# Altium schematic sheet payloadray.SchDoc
size A4
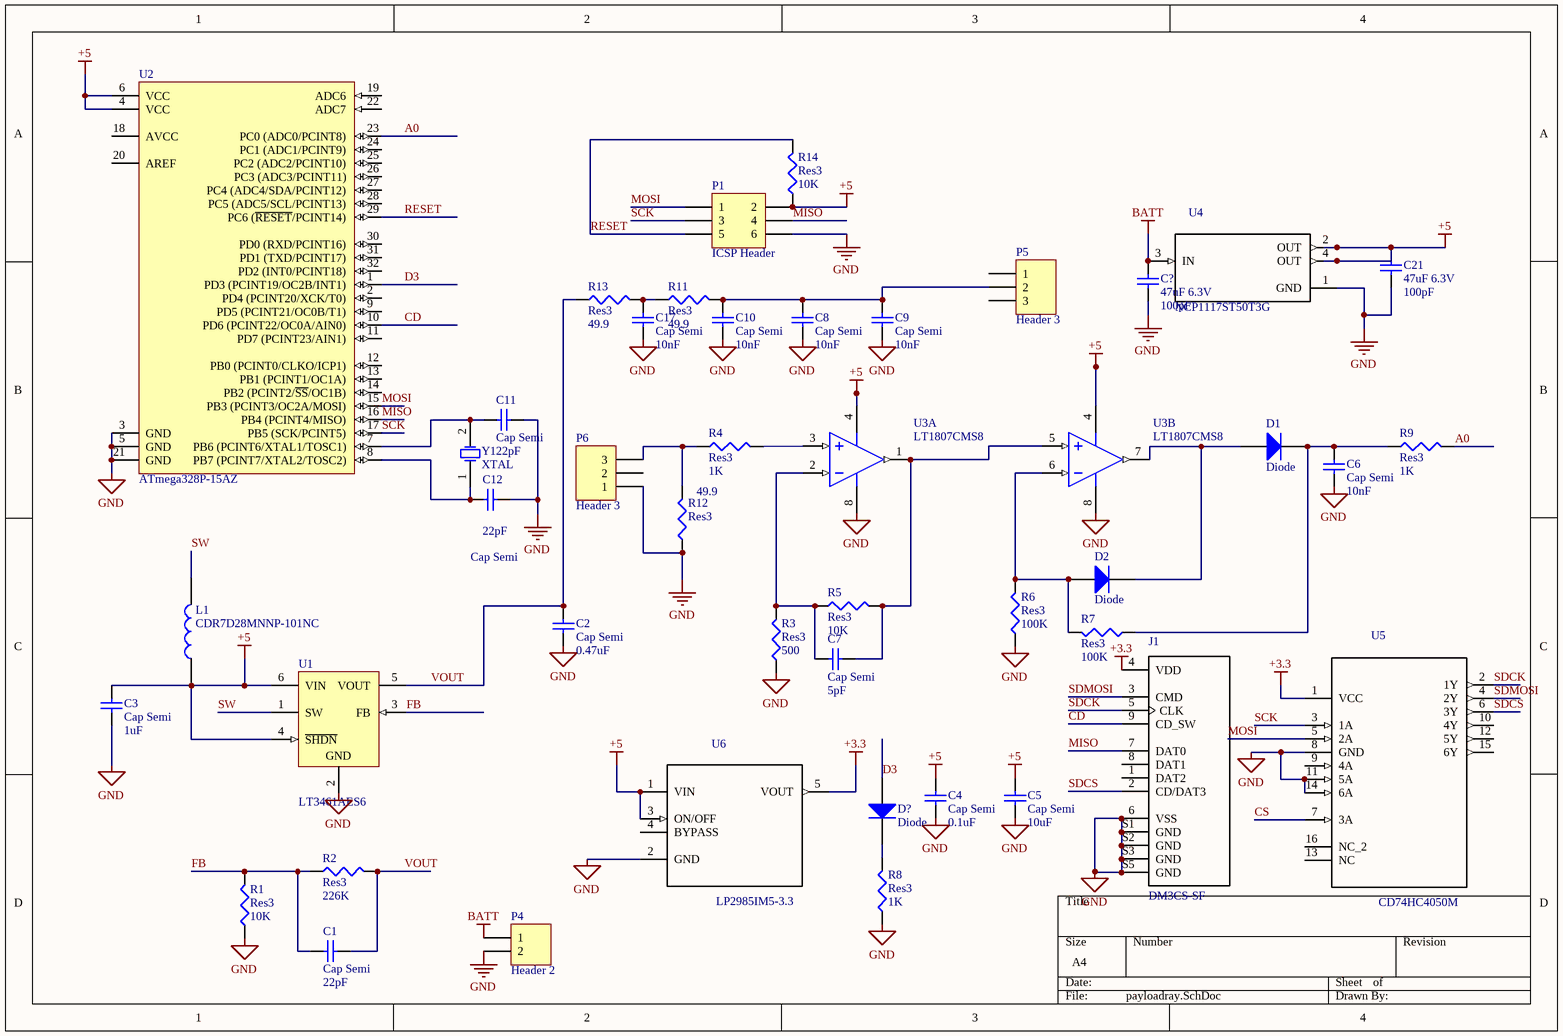
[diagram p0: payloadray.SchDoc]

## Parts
C1  Cap Semi  value 22pF  [C1206]
C2  Cap Semi  value 0.47uF  [C1206]
C3  Cap Semi  value 1uF  [C1206]
C4  Cap Semi  value 0.1uF  [C1206]
C5  Cap Semi  value 10uF  [C1206]
C6  Cap Semi  value 10nF  [C1206]
C7  Cap Semi  value 5pF  [C1206]
C8  Cap Semi  value 10nF  [C1206]
C9  Cap Semi  value 10nF  [C1206]
C10  Cap Semi  value 10nF  [C1206]
C11  Cap Semi  value 22pF  [C1206]
C12  Cap Semi  value 22pF  [C1206]
C17  Cap Semi  value 10nF  [C1206]
C21  47uF 6.3V  value 100pF  [1206]
C?  47uF 6.3V  value 100pF  [1206]
D1  Diode  [SMC]
D2  Diode  [SMC]
D?  Diode  [SMC]
J1  DM3CS-SF  [HRS_DM3CS-SF_DM3CS-SF(Primary)]
L1  CDR7D28MNNP-101NC  [CDR7D28MNNP101NC]
P1  ICSP Header  [HDR2X3]
P4  Header 2  [HDR1X2]
P5  Header 3  [HDR1X3]
P6  Header 3  [HDR1X3]
R1  Res3  value 10K  [J1-0603]
R2  Res3  value 226K  [J1-0603]
R3  Res3  value 500  [J1-0603]
R4  Res3  value 1K  [J1-0603]
R5  Res3  value 10K  [J1-0603]
R6  Res3  value 100K  [J1-0603]
R7  Res3  value 100K  [J1-0603]
R8  Res3  value 1K  [J1-0603]
R9  Res3  value 1K  [J1-0603]
R11  Res3  value 49.9  [J1-0603]
R12  Res3  value 49.9  [J1-0603]
R13  Res3  value 49.9  [J1-0603]
R14  Res3  value 10K  [J1-0603]
U1  LT3461AES6  [LT-S6-6-TSOT-23_N]
U2  ATmega328P-15AZ  [32MA_N]
U3  LT1807CMS8  [LT-MS8-8_N]  (parts A,B of 2)
U4  NCP1117ST50T3G  [SOT230P700X180-4N]
U5  CD74HC4050M  [SOIC127P600X175-16N]
U6  LP2985IM5-3.3  [SOT95P285X120-5N]
Y1  XTAL  [R38]

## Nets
+3.3: J1.4(VDD) U5.1(VCC) U6.5(VOUT)
+5: C3.2 C4.2 C5.2 C21.1 L1.1 P1.2 R14.1 U1.4(~{SHDN}) U1.6(VIN) U2.4(VCC) U2.6(VCC) U3.4(V-) U4.2(OUT) U4.4(OUT) U6.1(VIN) U6.3(ON/OFF)
BATT: C?.1 P4.1 U4.3(IN)
GND: C2.1 C3.1 C4.1 C5.1 C6.1 C8.1 C9.1 C10.1 C11.1 C12.1 C17.1 C21.2 C?.2 J1.6(VSS) J1.S1(GND) J1.S2(GND) J1.S3(GND) J1.S5(GND) P1.6 P4.2 P6.1 R1.1 R3.1 R6.1 R8.1 R12.1 U1.2(GND) U2.3(GND) U2.5(GND) U2.21(GND) U3.8(V+) U4.1(GND) U5.8(GND) U5.11(5A) U5.14(6A) U6.2(GND)
A0: R9.2 U2.23(PC0_(ADC0/PCINT8))
CD: J1.9(CD_SW) U2.10(PD6_(PCINT22/OC0A/AIN0))
CS: U5.7(3A)
D3: D?.1(A) U2.1(PD3_(PCINT19/OC2B/INT1))
FB: C1.1 R1.2 R2.1 U1.3(FB)
MISO: J1.7(DAT0) P1.4 U2.16(PB4_(PCINT4/MISO))
MOSI: P1.1 U2.15(PB3_(PCINT3/OC2A/MOSI)) U5.5(2A)
RESET: P1.5 R14.2 U2.29(PC6_(~{RESET}/PCINT14))
SCK: P1.3 U2.17(PB5_(SCK/PCINT5)) U5.3(1A)
SDCK: J1.5(CLK) U5.2(1Y)
SDCS: J1.2(CD/DAT3) U5.6(3Y)
SDMOSI: J1.3(CMD) U5.4(2Y)
SW: L1.2 U1.1(SW)
VOUT: C1.2 C2.2 R2.2 R13.1 U1.5(VOUT)
NetC6_2: C6.2 D1.2(K) R7.1 R9.1
NetC7_1: C7.1 R3.2 R5.1 U3.2(-IN_A)
NetC7_2: C7.2 R5.2 U3.1(OUT_A) U3.5(+IN_B)
NetC8_2: C8.2 C9.2 C10.2 P5.2 R11.2
NetC11_2: C11.2 U2.7(PB6_(PCINT6/XTAL1/TOSC1)) Y1.2(OSC2)
NetC12_2: C12.2 U2.8(PB7_(PCINT7/XTAL2/TOSC2)) Y1.1(OSC1)
NetC17_2: C17.2 R11.1 R13.2
NetD1_1: D1.1(A) D2.2(K) U3.7(OUT_B)
NetD2_1: D2.1(A) R6.2 R7.2 U3.6(-IN_B)
NetD?_2: D?.2(K) R8.2
NetP6_3: P6.3 R4.1 R12.2
NetR4_2: R4.2 U3.3(+IN_A)

Not connected (* = marked no-connect by the designer): J1 1(DAT2) 8(DAT1); P5 1 3; P6 2; U2 2(PD4_(PCINT20/XCK/T0)) 9(PD5_(PCINT21/OC0B/T1)) 11(PD7_(PCINT23/AIN1)) 12(PB0_(PCINT0/CLKO/ICP1)) 13(PB1_(PCINT1/OC1A)) 14(PB2_(PCINT2/~{SS}/OC1B)) 18(AVCC) 19(ADC6) 20(AREF) 22(ADC7) 24(PC1_(ADC1/PCINT9)) 25(PC2_(ADC2/PCINT10)) 26(PC3_(ADC3/PCINT11)) 27(PC4_(ADC4/SDA/PCINT12)) 28(PC5_(ADC5/SCL/PCINT13)) 30(PD0_(RXD/PCINT16)) 31(PD1_(TXD/PCINT17)) 32(PD2_(INT0/PCINT18)); U5 9(4A) 10(4Y) 12(5Y) 13(NC) 15(6Y) 16(NC_2); U6 4(BYPASS)

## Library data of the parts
C1-C12 C17 = Cap Semi: Capacitor (Semiconductor SIM Model)
C21 C? = C1206: Ceramic Chip Capacitor - Standard
D1 D2 D? = Diode: Default Diode
J1 = DM3CS-SF: Conn Micro SD Card HDR 8 POS 1.1mm Solder RA SMD Embossed T/R 0.5A; MF: Hirose
L1 = CDR7D28MNNP-101NC: Fixed Inductors 100uH .65A; Manufacturer_Name: Sumida; Geometry.Height: 3mm
P1 = Header 3X2: Header, 3-Pin, Dual row
P4 = Header 2: Header, 2-Pin
P5 P6 = Header 3: Header, 3-Pin
R1-R9 R11-R14 = Res3: Resistor
U1 = LT3461AES6: 3 MHz Step-Up DC/DC Converter with Integrated Schottky, 6-pin SOT23 (S6-6), -40 to 85 degC; Manufacturer: Linear Technology; Number of Outputs: 1
U2 = ATmega328P-15AZ: 8-bit Automotive AVR Microcontroller, 32KB Flash, 1KB EEPROM, 2KB SRAM, 23 GPIO pins, Automotive Grade (-40°C to +125°C), 32-Pin TQFP
U3 = LT1807CMS8: Dual Channel, High Speed, Low Noise Precision Operational Amplifier, 325 MHz Typical GBW, 125 V/us Typical SR, 2.5 to 12.6 V, 8-Pin SOP (MS8-8), Commercial; Linear Technology Part Number: LT1807; Manufacturer: Linear Technology; Channels (#): 2; GBW (MHz) Typical: 325; Is (mA) Typical: 9; SR (V/us) Typical: 125; Vos (mV) Guaranteed: 0.55; Vos (mV) Typical: 0.1; Vs Max (V): 12.6; Vs Min (V): 2.5
U4 = NCP1117ST50T3G: MF: ON Semiconductor
U5 = CD74HC4050M: MF: Texas
U6 = LP2985IM5-3.3: Micropower 150 mA Low-Noise Ultra Low-Dropout Regulator in SOT-23 and micro SMD Packages 5-SOT-23 -40 to 125; MF: Texas Instruments
Y1 = XTAL: Crystal Oscillator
